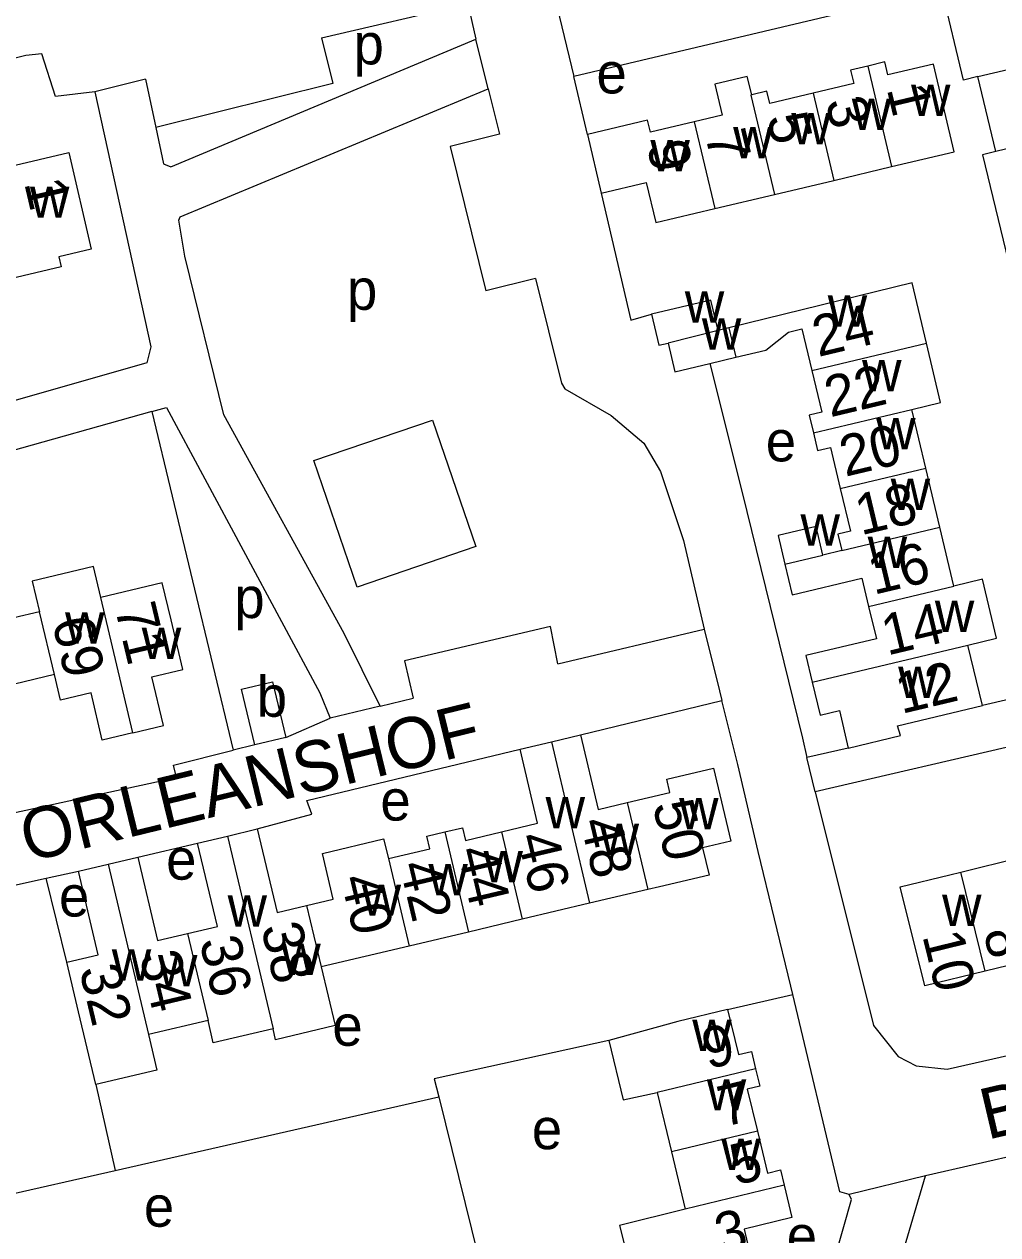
# Model space of a CAD drawing. Extents: x 157768 to 159790, y 387230 to 389604.
# Drawn here: x 159176.8 to 159272.3, y 388362 to 388480.9 of the extents above; entities that cross this region are included whole.
import ezdxf

# ---------------------------------------------------------------- set-up
doc = ezdxf.new("R2010")
doc.units = 0
for name, color, linetype in [('BLT_Basislijn', 7, 'Continuous'), ('BLT_Bebouwing', 7, 'Continuous'), ('BLT_Centroide', 7, 'Continuous'), ('BLT_Huisnummer', 7, 'Continuous'), ('BLT_Huisnummer_ tussenligend', 7, 'Continuous'), ('BLT_Huisnummer_reeks', 7, 'Continuous'), ('BLT_Onderverdeling_panden', 7, 'Continuous'), ('BLT_Straatnaam', 7, 'Continuous')]:
    doc.layers.add(name, color=color, linetype=linetype)

msp = doc.modelspace()

# ---------------------------------------------------------------- linework, layer by layer
at = {"layer": 'BLT_Basislijn'}
for p, q in [((159205.99, 388479.54), (159220.35, 388482.9)), ((159220.35, 388482.9), (159221.15, 388479.43)), ((159222.35, 388474.55), (159221.15, 388479.43)), ((159188.72, 388475.5), (159183.75, 388474.26)), ((159188.72, 388475.5), (159189.74, 388470.74)), ((159232.08, 388470.07), (159230.76, 388475.76)), ((159207.1, 388475.06), (159189.74, 388470.74)), ((159222.35, 388474.55), (159223.46, 388470.09)), ((159223.46, 388470.09), (159218.61, 388468.88)), ((159226.99, 388455.93), (159222.13, 388454.72)), ((159189.35, 388442.87), (159197.34, 388409.62)), ((159229.19, 388418.09), (159243.55, 388421.5)), ((159211.74, 388413.95), (159206.85, 388412.76)), ((159211.74, 388413.95), (159214.99, 388414.72)), ((159231.41, 388411.12), (159245.28, 388414.5)), ((159289.69, 388413.74), (159254.44, 388405.52)), ((159202.48, 388410.86), (159206.85, 388412.76)), ((159199.46, 388410.14), (159197.34, 388409.62)), ((159257.66, 388409.83), (159253.62, 388408.91)), ((159254.44, 388405.52), (159253.62, 388408.91)), ((159187.97, 388399.11), (159193.84, 388400.5)), ((159178.99, 388397.04), (159182.14, 388397.73)), ((159181.01, 388388.8), (159178.99, 388397.04)), ((159245.83, 388384.15), (159252.25, 388385.65)), ((159183.86, 388376.79), (159185.74, 388368.37)), ((159185.74, 388368.37), (159217.5, 388375.58)), ((159217.5, 388375.58), (159221.36, 388359.94)), ((159292.72, 388374.1), (159265.24, 388367.85)), ((159167.78, 388364.29), (159185.74, 388368.37)), ((159265.24, 388367.85), (159257.75, 388366.01)), ((159261.4, 388354.78), (159265.24, 388367.85))]:
    msp.add_line(p, q, dxfattribs=at)
for points in [[(159232.55, 388499.28), (159227.69, 388488.52), (159230.76, 388475.76)], [(159270.4, 388475.74), (159268.99, 388475.4), (159266.84, 388484.32), (159230.76, 388475.76)], [(159189.74, 388470.74), (159190.49, 388467.19), (159191.2, 388466.9), (159221.15, 388479.43)], [(159205.99, 388479.54), (159207.1, 388475.06)], [(159183.75, 388474.26), (159179.89, 388473.78), (159178.57, 388477.97), (159176.99, 388477.81), (159106.11, 388459.93)], [(159183.75, 388474.26), (159189.25, 388449.23), (159188.87, 388447.64), (159160.69, 388439.6), (159127.47, 388433.94), (159100.65, 388426.26)], [(159211.74, 388413.95), (159208.2, 388421.09), (159196.42, 388442.54), (159192.57, 388458.11), (159191.98, 388461.65), (159192.13, 388461.99), (159222.35, 388474.55)], [(159218.61, 388468.88), (159222.13, 388454.72)], [(159272.14, 388468.4), (159270.83, 388468.08), (159282.56, 388419.71), (159281.56, 388416.49), (159270.83, 388413.99)], [(159233.43, 388464.3), (159236.34, 388451.85), (159238.36, 388452.41)], [(159226.99, 388455.93), (159229.54, 388445.66), (159229.86, 388445.09), (159234.41, 388442.48), (159237.6, 388439.77), (159239.25, 388436.97), (159241.5, 388430.2), (159243.55, 388421.5)], [(159244.1, 388447.59), (159247.25, 388434.9), (159253.17, 388410.8), (159253.62, 388408.91)], [(159189.35, 388442.87), (159159.54, 388434.5), (159133.68, 388430.36), (159100.76, 388421.61)], [(159189.35, 388442.87), (159190.78, 388443.27), (159205.83, 388415.24), (159206.85, 388412.76)], [(159209.49, 388425.63), (159205.25, 388438.05), (159216.89, 388442.03)], [(159216.89, 388442.03), (159221.13, 388429.61), (159209.49, 388425.63)], [(159229.19, 388418.09), (159228.46, 388421.77), (159214.15, 388418.39)], [(159243.55, 388421.5), (159245.05, 388415.44), (159245.28, 388414.5)], [(159214.15, 388418.39), (159214.99, 388414.72)], [(159252.25, 388385.65), (159252.05, 388386.46), (159248.83, 388399.66), (159246.83, 388408.23), (159245.28, 388414.5)], [(159171.05, 388402.47), (159191.76, 388406.94), (159191.46, 388408.16), (159197.34, 388409.62)], [(159199.68, 388401.89), (159205.05, 388403.35), (159204.56, 388404.69), (159225.47, 388409.72)], [(159254.44, 388405.52), (159260.14, 388382.59), (159262.58, 388379.56), (159264.32, 388378.64), (159267.37, 388378.29), (159297.85, 388385.21)], [(159152.87, 388388.5), (159152.26, 388391.13), (159178.99, 388397.04)], [(159257.75, 388366.01), (159256.83, 388366.27), (159252.25, 388385.65)], [(159234.18, 388381.13), (159217.06, 388377.35), (159217.5, 388375.58)], [(159224.51, 388346.8), (159224.74, 388345.9), (159253.49, 388352.57), (159254.22, 388353.05), (159254.84, 388354.45), (159257.98, 388365.51), (159257.75, 388366.01)]]:
    msp.add_lwpolyline(points, dxfattribs=at)
at = {"layer": 'BLT_Bebouwing'}
for p, q in [((159270.4, 388475.74), (159276.16, 388477.1)), ((159272.14, 388468.4), (159270.4, 388475.74)), ((159277.89, 388469.76), (159272.14, 388468.4)), ((159256.26, 388465.56), (159261.93, 388466.91)), ((159250.42, 388464.17), (159256.26, 388465.56)), ((159244.58, 388462.78), (159250.42, 388464.17)), ((159265.28, 388437.3), (159263.91, 388443.07)), ((159266.66, 388431.51), (159265.28, 388437.3)), ((159255.19, 388428.78), (159254.52, 388431.57)), ((159268.04, 388425.72), (159266.66, 388431.51)), ((159257.03, 388429.22), (159255.19, 388428.78)), ((159270.83, 388413.99), (159269.42, 388419.93)), ((159254.13, 388416.3), (159254.9, 388413.05)), ((159262.51, 388412), (159270.83, 388413.99)), ((159202.48, 388410.86), (159199.46, 388410.14)), ((159225.47, 388409.72), (159228.55, 388410.44)), ((159228.55, 388410.44), (159231.41, 388411.12)), ((159196.76, 388401.19), (159199.68, 388401.89)), ((159193.84, 388400.5), (159196.76, 388401.19)), ((159182.14, 388397.73), (159185.05, 388398.42)), ((159185.05, 388398.42), (159187.97, 388399.11)), ((159268.73, 388397.66), (159274.51, 388399.08)), ((159238, 388395.94), (159232.3, 388394.59)), ((159232.3, 388394.59), (159225.69, 388393.02)), ((159225.69, 388393.02), (159220.4, 388391.77)), ((159220.4, 388391.77), (159214.59, 388390.39)), ((159194.87, 388383.09), (159189.01, 388381.7)), ((159238.91, 388376.01), (159240.32, 388370.18)), ((159240.32, 388370.18), (159241.67, 388364.57))]:
    msp.add_line(p, q, dxfattribs=at)
for points in [[(159259.59, 388476.78), (159257.9, 388476.38), (159258.21, 388475.08), (159254.22, 388474.13)], [(159261.93, 388466.91), (159268.07, 388468.37), (159266.03, 388476.97), (159261.57, 388475.91), (159261.27, 388477.18), (159259.59, 388476.78)], [(159248.2, 388473.94), (159247.77, 388475.75), (159244.58, 388475), (159245.31, 388471.95), (159242.56, 388471.3)], [(159254.22, 388474.13), (159249.98, 388473.12), (159249.7, 388474.3), (159248.2, 388473.94)], [(159242.56, 388471.3), (159238.26, 388470.28), (159237.98, 388471.47), (159232.08, 388470.07)], [(159232.08, 388470.07), (159233.43, 388464.3)], [(159172.12, 388464.58), (159175.73, 388465.43), (159175.37, 388466.93), (159181.19, 388468.29), (159183.41, 388458.79), (159180.23, 388458.05), (159180.46, 388457.06), (159174.21, 388455.6)], [(159233.43, 388464.3), (159237.85, 388465.35), (159238.79, 388461.41), (159244.58, 388462.78)], [(159265.34, 388449.56), (159263.93, 388455.5), (159245.95, 388451.09)], [(159244.9, 388450.83), (159244.19, 388453.79), (159238.36, 388452.41)], [(159238.36, 388452.41), (159239.09, 388449.37), (159240, 388449.59)], [(159245.95, 388451.09), (159244.9, 388450.83)], [(159246.64, 388448.19), (159249.58, 388448.89), (159251.81, 388450.67), (159253.12, 388450.98), (159254.1, 388446.89)], [(159240, 388449.59), (159240.67, 388446.77)], [(159263.91, 388443.07), (159266.73, 388443.76), (159265.34, 388449.56)], [(159244.1, 388447.59), (159246.64, 388448.19)], [(159240.67, 388446.77), (159244.1, 388447.59)], [(159254.1, 388446.89), (159255.07, 388442.8), (159253.84, 388442.51), (159254.26, 388440.78)], [(159254.26, 388440.78), (159254.67, 388439.05), (159255.93, 388439.35), (159256.89, 388435.3)], [(159256.89, 388435.3), (159257.89, 388431.11), (159256.65, 388430.82), (159257.03, 388429.22)], [(159254.52, 388431.57), (159250.78, 388430.68), (159251.44, 388427.89)], [(159251.44, 388427.89), (159252.16, 388424.88), (159259.01, 388426.51), (159259.67, 388423.73)], [(159184.33, 388424.62), (159183.61, 388427.64), (159177.61, 388426.21), (159178.33, 388423.2)], [(159187.49, 388411.33), (159190.49, 388412.04), (159189.36, 388416.81), (159192.4, 388417.53), (159191.24, 388422.4), (159190.37, 388426.06), (159184.33, 388424.62)], [(159269.42, 388419.93), (159272.23, 388420.61), (159270.84, 388426.4), (159268.04, 388425.72)], [(159178.33, 388423.2), (159175.81, 388422.6), (159175.19, 388425.19), (159168.99, 388423.72)], [(159259.67, 388423.73), (159260.43, 388420.55), (159253.51, 388418.91), (159254.13, 388416.3)], [(159179.79, 388417.04), (159172.86, 388415.39), (159173.18, 388414.04), (159171.39, 388413.62), (159171.06, 388414.99)], [(159187.49, 388411.33), (159184.49, 388410.61), (159183.39, 388415.25), (159180.39, 388414.53), (159179.79, 388417.04)], [(159199.46, 388410.14), (159198.16, 388415.61), (159201.18, 388416.32), (159202.48, 388410.86)], [(159254.9, 388413.05), (159256.81, 388413.5), (159257.66, 388409.83)], [(159257.66, 388409.83), (159262.8, 388411.05), (159262.51, 388412)], [(159231.41, 388411.12), (159233.14, 388403.8), (159235.98, 388404.47)], [(159223.65, 388401.6), (159227.19, 388402.44), (159225.47, 388409.72)], [(159235.98, 388404.47), (159240.17, 388405.47), (159239.86, 388406.76), (159244.46, 388407.85), (159246.16, 388400.7), (159243.38, 388400.04), (159244.01, 388397.36), (159239.14, 388396.21), (159238, 388395.94)], [(159199.68, 388401.89), (159201.63, 388393.69), (159204.53, 388394.38)], [(159218.08, 388401.59), (159219.83, 388402), (159220.12, 388400.76), (159223.65, 388401.6)], [(159204.53, 388394.38), (159207.15, 388394.99), (159206.08, 388399.48), (159212.07, 388400.93), (159212.55, 388398.99)], [(159212.55, 388398.99), (159216.62, 388399.95), (159216.33, 388401.17), (159218.08, 388401.59)], [(159192.84, 388391.63), (159195.78, 388392.32), (159193.84, 388400.5)], [(159187.97, 388399.11), (159189.91, 388390.93), (159192.84, 388391.63)], [(159181.01, 388388.8), (159184.08, 388389.53), (159182.14, 388397.73)], [(159271.12, 388387.92), (159265.17, 388386.49), (159262.78, 388396.2), (159267.64, 388397.39), (159268.73, 388397.66)], [(159214.59, 388390.39), (159205.97, 388388.34)], [(159183.86, 388376.79), (159182.16, 388383.94), (159181.01, 388388.8)], [(159276.9, 388389.32), (159271.12, 388387.92)], [(159205.97, 388388.34), (159207.34, 388382.58), (159201.49, 388381.19), (159201.24, 388382.28)], [(159245.83, 388384.15), (159240.96, 388382.98), (159234.18, 388381.13)], [(159245.83, 388384.15), (159246.89, 388379.73), (159248.17, 388380.04), (159248.58, 388378.34)], [(159201.24, 388382.28), (159195.38, 388380.89), (159194.87, 388383.09)], [(159189.01, 388381.7), (159189.84, 388378.2), (159183.86, 388376.79)], [(159234.18, 388381.13), (159235.59, 388375.31), (159238.91, 388376.01)], [(159248.58, 388378.34), (159248.99, 388376.65), (159247.76, 388376.35), (159248.76, 388372.22)], [(159248.76, 388372.22), (159249.75, 388368.1), (159251.01, 388368.41), (159251.37, 388366.92)], [(159251.37, 388366.92), (159252.14, 388363.74), (159247.45, 388362.61), (159248.16, 388359.66), (159245.98, 388359.13)], [(159241.67, 388364.57), (159235.24, 388362.97), (159236.71, 388357.1)]]:
    msp.add_lwpolyline(points, dxfattribs=at)
at = {"layer": 'BLT_Onderverdeling_panden'}
for p, q in [((159259.59, 388476.78), (159261.93, 388466.91)), ((159254.22, 388474.13), (159256.26, 388465.56)), ((159242.56, 388471.3), (159244.58, 388462.78)), ((159244.9, 388450.83), (159240, 388449.59)), ((159245.95, 388451.09), (159246.64, 388448.19)), ((159254.1, 388446.89), (159265.34, 388449.56)), ((159254.26, 388440.78), (159263.91, 388443.07)), ((159256.89, 388435.3), (159265.28, 388437.3)), ((159251.44, 388427.89), (159255.19, 388428.78)), ((159259.67, 388423.73), (159268.04, 388425.72)), ((159187.49, 388411.33), (159184.33, 388424.62)), ((159179.79, 388417.04), (159178.33, 388423.2)), ((159254.13, 388416.3), (159269.42, 388419.93)), ((159228.55, 388410.44), (159232.3, 388394.59)), ((159235.98, 388404.47), (159238, 388395.94)), ((159196.76, 388401.19), (159201.24, 388382.28)), ((159218.08, 388401.59), (159220.4, 388391.77)), ((159223.65, 388401.6), (159225.69, 388393.02)), ((159185.05, 388398.42), (159189.01, 388381.7)), ((159212.55, 388398.99), (159214.59, 388390.39)), ((159271.12, 388387.92), (159268.73, 388397.66)), ((159204.53, 388394.38), (159205.97, 388388.34)), ((159192.84, 388391.63), (159194.87, 388383.09)), ((159248.58, 388378.34), (159238.91, 388376.01)), ((159248.76, 388372.22), (159240.32, 388370.18)), ((159251.37, 388366.92), (159241.67, 388364.57))]:
    msp.add_line(p, q, dxfattribs=at)
for points in [[(159248.2, 388473.94), (159248.1, 388473.92), (159250.42, 388464.17)], [(159257.03, 388429.22), (159266.66, 388431.51)]]:
    msp.add_lwpolyline(points, dxfattribs=at)

# ---------------------------------------------------------------- texts
at = {"layer": 'BLT_Centroide'}
for s, p in [('p', (159209.14, 388476.94)), ('e', (159232.97, 388474.09)), ('w', (159263.83, 388471.89)), ('w', (159258.02, 388470.5)), ('w', (159252.08, 388469.09)), ('w', (159246.38, 388467.72)), ('w', (159238.26, 388466.44)), ('w', (159177.39, 388461.88)), ('p', (159208.49, 388452.85)), ('w', (159241.64, 388451.59)), ('w', (159255.66, 388451.19)), ('w', (159243.31, 388448.94)), ('w', (159259.03, 388444.84)), ('w', (159260.41, 388439.16)), ('e', (159249.58, 388437.97)), ('w', (159261.84, 388433.19)), ('w', (159252.99, 388429.69)), ('w', (159259.58, 388427.5)), ('p', (159197.44, 388422.59)), ('w', (159180.83, 388420.09)), ('w', (159266.17, 388421.22)), ('w', (159188.36, 388418.56)), ('w', (159262.57, 388414.75)), ('b', (159199.64, 388412.9)), ('e', (159211.77, 388402.71)), ('w', (159227.98, 388401.94)), ('w', (159241.08, 388401.86)), ('w', (159233.28, 388399.33)), ('e', (159190.75, 388396.91)), ('w', (159221.89, 388396.66)), ('w', (159216.48, 388395.38)), ('e', (159180.24, 388393.29)), ('w', (159209.94, 388393.36)), ('w', (159196.78, 388392.31)), ('w', (159266.88, 388392.36)), ('w', (159185.42, 388387)), ('w', (159202.05, 388387.55)), ('w', (159189.95, 388386.44)), ('e', (159207.06, 388380.6)), ('w', (159242.37, 388380.09)), ('w', (159243.8, 388374.25)), ('e', (159226.63, 388370.45)), ('w', (159245.22, 388368.41)), ('e', (159188.57, 388362.84)), ('e', (159251.64, 388359.93))]:
    msp.add_text(s, height=4, dxfattribs=at).set_placement(p)
at = {"layer": 'BLT_Huisnummer'}
for s, rotation, p in [('1', 283.3692, (159261.44, 388474.55)), ('5', 283.3649, (159249.65, 388471.74)), ('9', 283.3727, (159237.88, 388469.01)), ('1', 283.1491, (159176.81, 388465.31)), ('24', 13.3897, (159254.71, 388448.21)), ('20', 13.3897, (159257.37, 388436.45)), ('16', 13.3897, (159260.17, 388424.86)), ('71', 283.3707, (159185.7, 388423.6)), ('12', 13.3897, (159262.89, 388413.17)), ('50', 283.3339, (159238.46, 388404.26)), ('44', 283.3339, (159219.28, 388399.78)), ('40', 283.3339, (159207.85, 388397.01)), ('36', 283.3339, (159194, 388390.9)), ('10', 283.7862, (159264.93, 388391.41)), ('32', 283.3339, (159182.21, 388388.11)), ('9', 13.5769, (159243.9, 388378.29))]:
    msp.add_text(s, height=4, rotation=rotation, dxfattribs=at).set_placement(p)
at = {"layer": 'BLT_Huisnummer_ tussenligend'}
for s, rotation, p in [('3', 283.3692, (159255.4, 388473.29)), ('7', 283.3649, (159243.6, 388470.05)), ('22', 13.3897, (159255.9, 388442.29)), ('18', 13.3897, (159258.91, 388430.7)), ('14', 13.3897, (159261.49, 388418.9)), ('69', 283.3733, (159179.54, 388422.25)), ('48', 283.3339, (159231.36, 388402.59)), ('46', 283.3339, (159225.18, 388401.12)), ('42', 283.3339, (159213.62, 388398.34)), ('38', 283.3339, (159200.04, 388392.24)), ('8', 283.7803, (159270.91, 388391.81)), ('34', 283.3339, (159188.11, 388389.47)), ('7', 13.5781, (159245.45, 388372.62)), ('5', 13.5781, (159246.63, 388366.89))]:
    msp.add_text(s, height=4, rotation=rotation, dxfattribs=at).set_placement(p)
at = {"layer": 'BLT_Huisnummer_reeks'}
msp.add_text('3', height=4, rotation=13.5781, dxfattribs=at).set_placement((159245.15, 388360.1))
at = {"layer": 'BLT_Straatnaam'}
for s, rotation, p in [('ORLEANSHOF', 13.7061, (159177.17, 388398.61)), ('BESANCONLAAN', 13.1868, (159271.3, 388371.36))]:
    msp.add_text(s, height=5, rotation=rotation, dxfattribs=at).set_placement(p)

doc.saveas('drawing.dxf')
